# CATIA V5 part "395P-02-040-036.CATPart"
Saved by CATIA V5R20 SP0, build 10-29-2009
Part number: 395P-02-040-036
Source: Unknown
Property "ARTICLENO": "395P-02-040-036"
Property "BOMINFO": "395P-02-040-036"
Property "CODE": "395P-02-040-036"
Property "D": "40.000"
Property "D1": "30.000"
Property "L": "118.000"
Property "L1": "56.000"
Property "L2": "12.000"
Property "L3": "40.000"
Property "L4": "5.000"
Property "LINA": "395P-02-040-036"
Property "M": "36.000"
Property "MAXLOAD": "2500 Kg"
Property "MDW": "5000 Kg"
Property "NB": "395P-02-040-036"
Property "NBSYN": "$CODE."
Property "NN": "395P"
Property "NT": "VDI 3366 Lifting Pins"
Property "R": "8.000"
Property "R1": "12.000"
Property "SUPPLIER": "CF"
Property "SW": "50.000"
Bounding box of the stored display mesh (mm): x -25 to 25, y -56 to 62, z -28.868 to 28.868
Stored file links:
  C:\Users\Utente\Desktop\3D files 395P\395P-02-040-036.CATPart
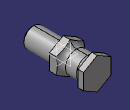
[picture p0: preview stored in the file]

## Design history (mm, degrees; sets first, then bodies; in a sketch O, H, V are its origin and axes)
Body1 "Geometry.1" (main body)
  Solid1 "395P-02-040-036.catpart": solid without history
